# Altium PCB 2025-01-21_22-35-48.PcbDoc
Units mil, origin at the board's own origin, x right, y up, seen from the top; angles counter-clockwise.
Board outline 2000 x 2400 mil, 4 copper layers (Top Layer, MidLayer1, MidLayer2, Bottom Layer); 12 components, 7 nets, 23 pads, 206 vias.
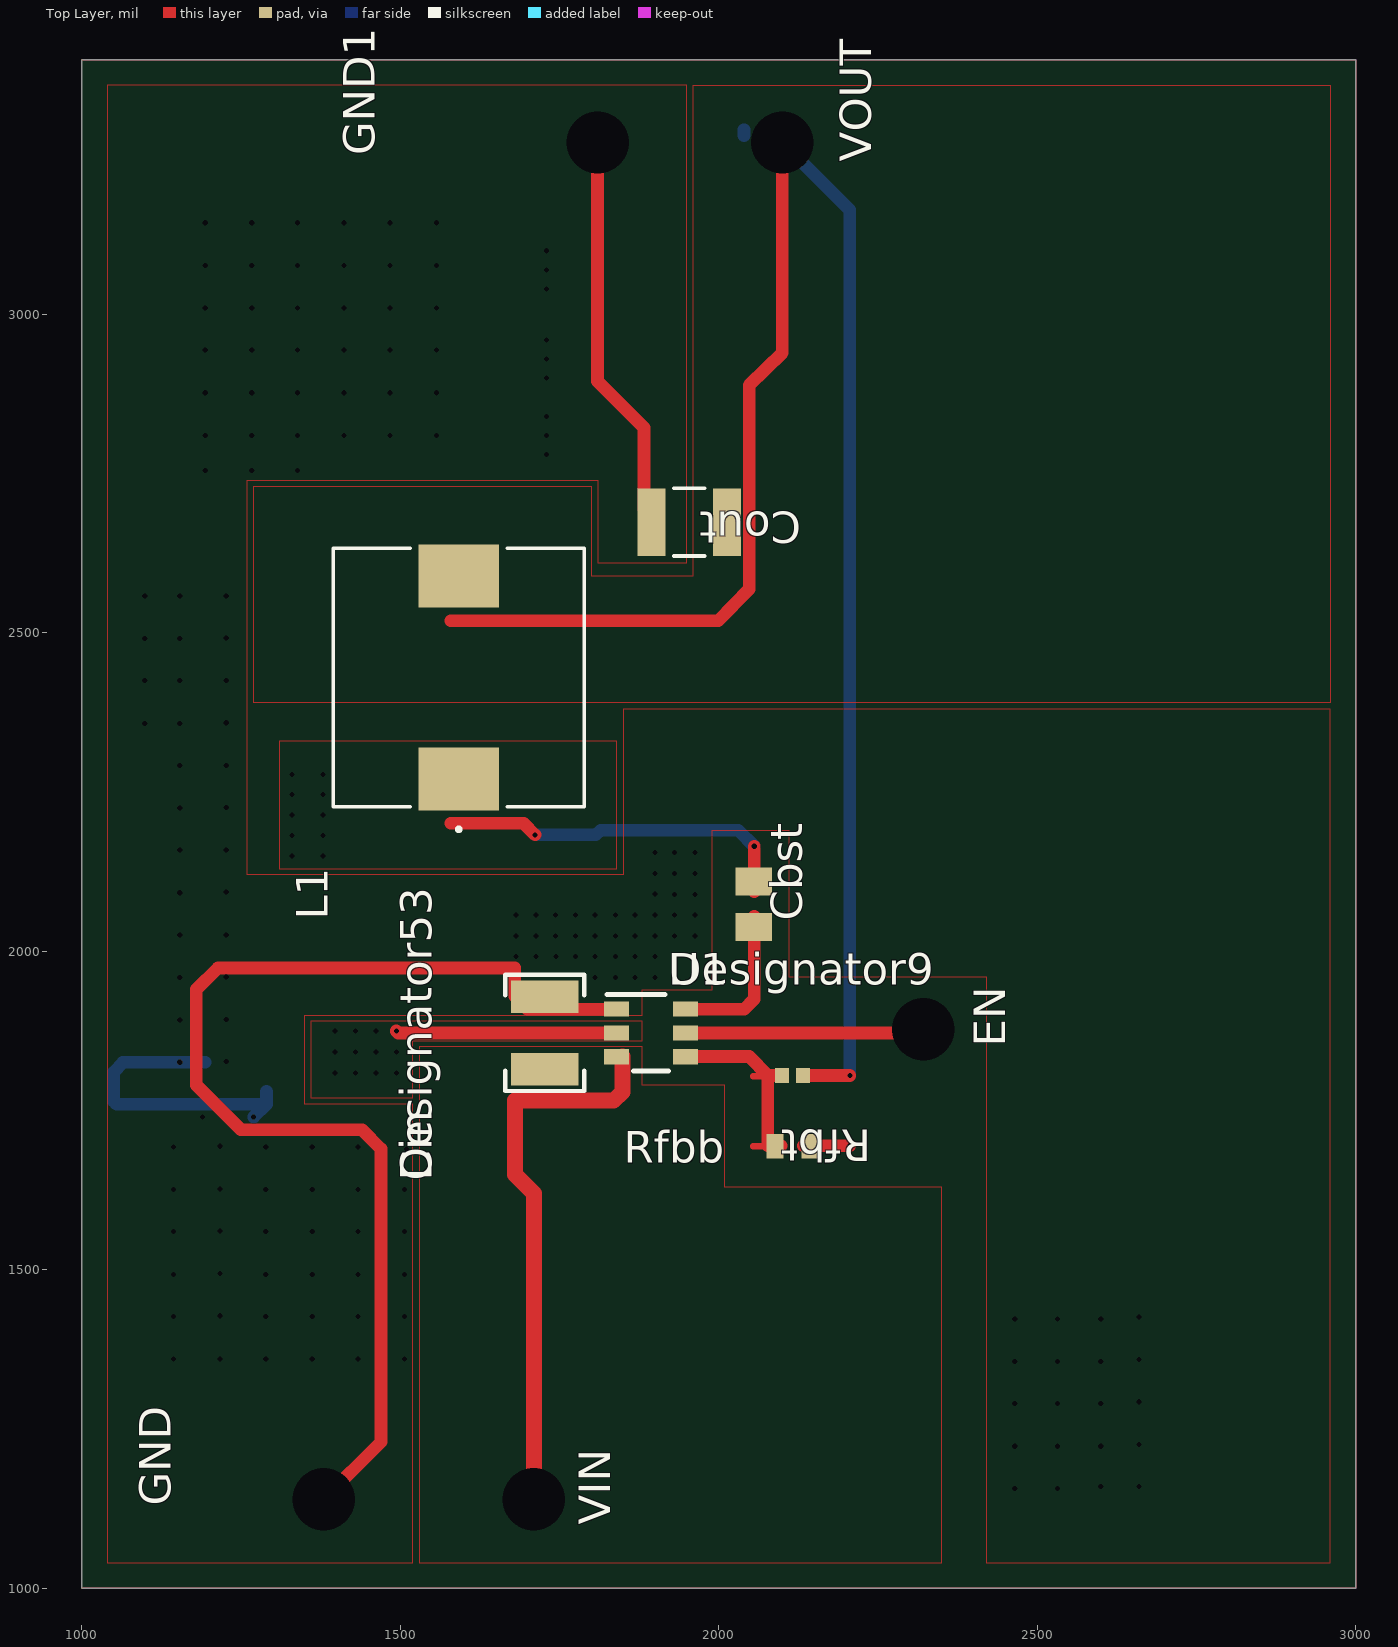
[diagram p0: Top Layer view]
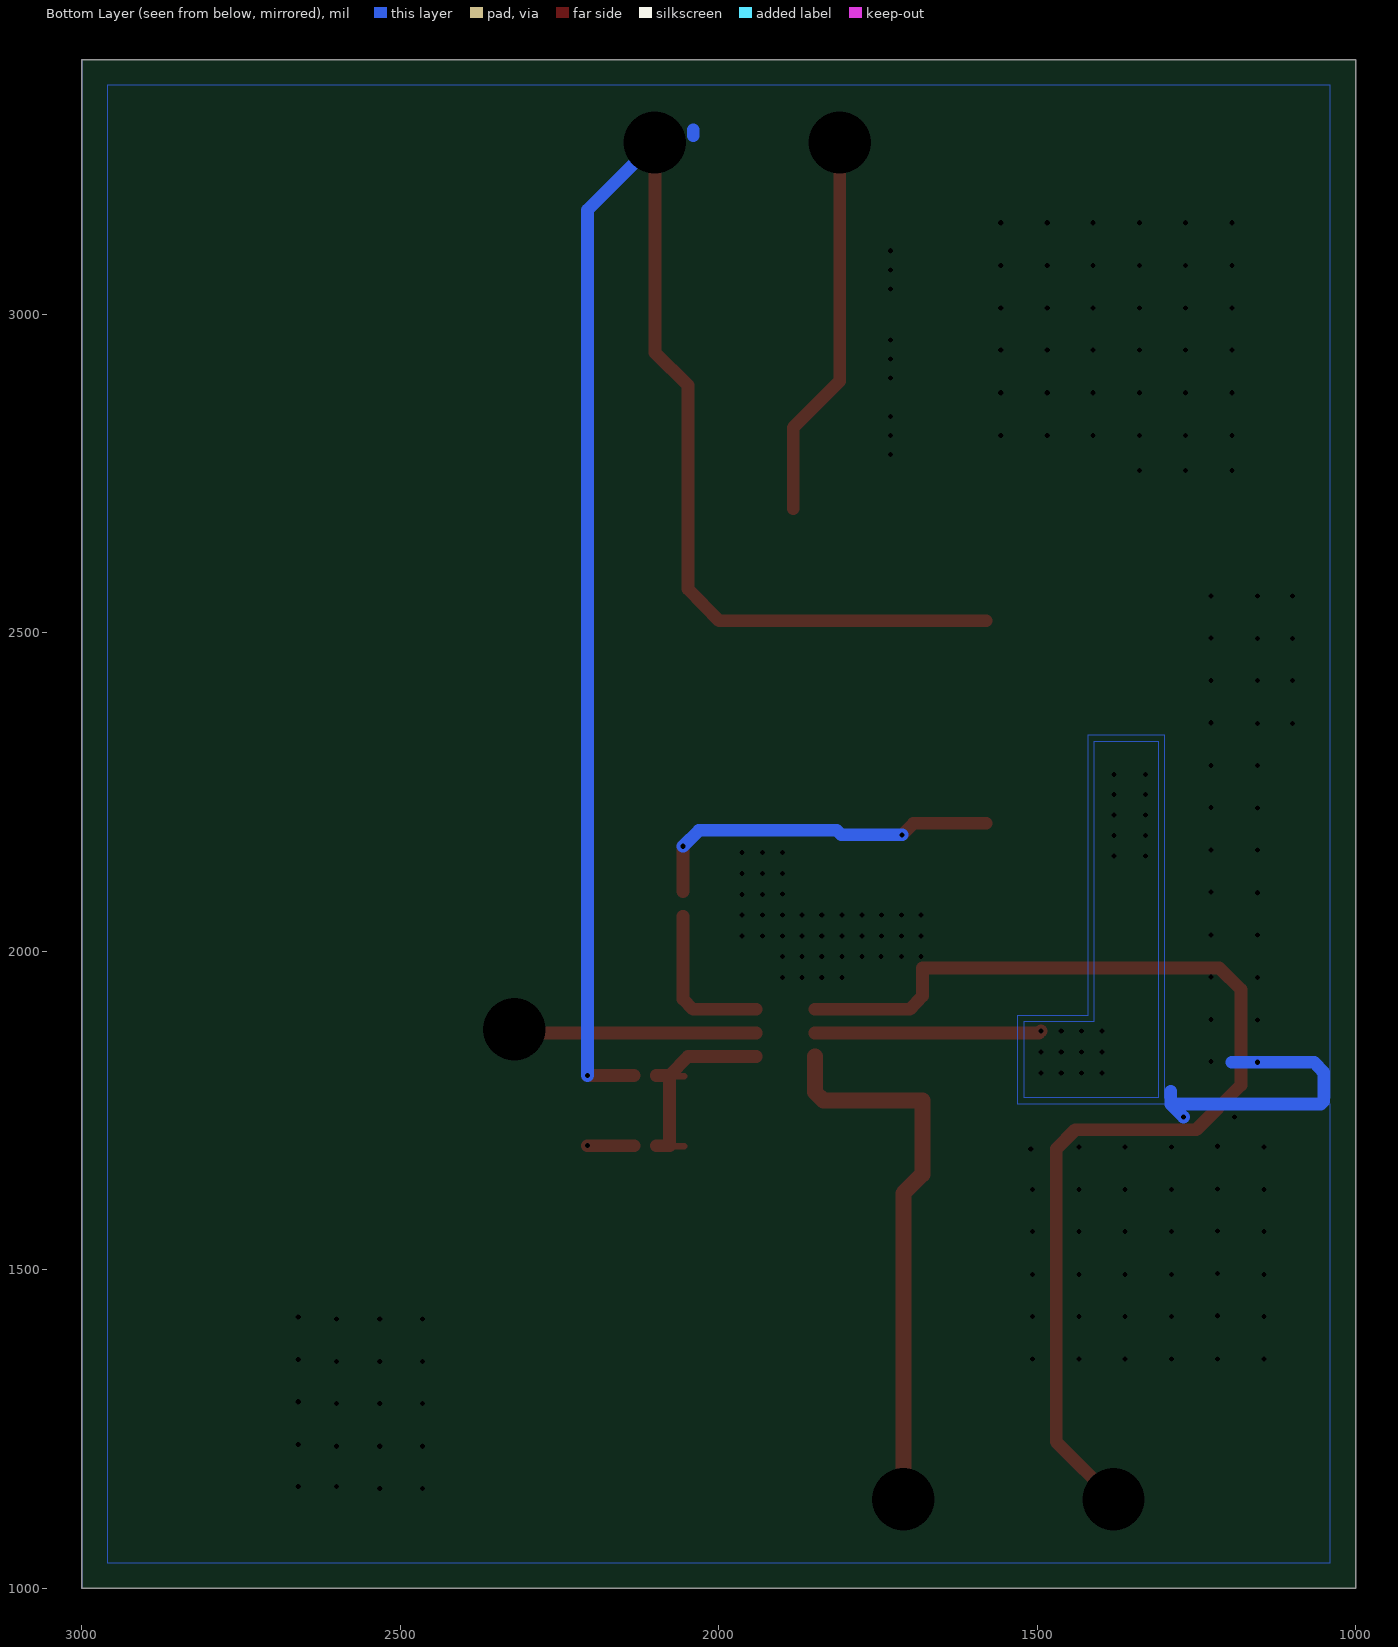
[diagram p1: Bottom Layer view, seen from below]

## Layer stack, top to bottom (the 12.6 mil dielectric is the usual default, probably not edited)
Top Layer: signal copper 1.4
Dielectric: core 12.6, FR-4, Dk 4.8
MidLayer1: signal copper 1.4
Dielectric: prepreg 12.6, FR-4, Dk 4.8
MidLayer2: signal copper 1.4
Dielectric: core 12.6, FR-4, Dk 4.8
Bottom Layer: signal copper 1.4

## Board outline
1000,1000 3000,1000 3000,3400 1000,3400

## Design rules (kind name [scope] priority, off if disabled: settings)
PlaneConnect [All] p0: scope1count=1 scope1_0_kind=Board scope1_0_value=Board scope2count=1 scope2_0_kind=Board scope2_0_value=Board commentlength=0 planeconnectstyle=Direct reliefexpansion=20 reliefentries=4 reliefconductorwidth=10 reliefairgap=10
PlaneConnect [All] p1: planeconnectstyle=Direct reliefexpansion=20 reliefentries=4 reliefconductorwidth=10 reliefairgap=10
PolygonConnect [All] p0: scope1count=1 scope1_0_kind=Board scope1_0_value=Board scope2count=1 scope2_0_kind=Board scope2_0_value=Board commentlength=0 connectstyle=Direct reliefconductorwidth=10 reliefentries=4 polygonreliefangle="90 Angle"
PolygonConnect [All] p1: connectstyle=Direct reliefconductorwidth=10 reliefentries=4 polygonreliefangle="90 Angle"

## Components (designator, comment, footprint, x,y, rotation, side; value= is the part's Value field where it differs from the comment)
Cbst "" 0805 2055,2074 r90 top
Cin "" 1210_270 1727,1872 r90 top
Cout "" 1210_280 1954,2674 r180 top
EN "" TP-1502 2320,1877 r90 top
GND "" TP-1502 1379,1139 r90 top
GND1 "" TP-1502 1809,3269 r90 top
L1 "" CLF10040 1592,2430 r90 top
Rfbb "" 0603 2116,1694 r0 top
Rfbt "" 0402 2116,1805 r180 top
U1 "" DDC0006A_N 1894,1872 r0 top
VIN "" TP-1502 1709,1139 r90 top
VOUT "" TP-1502 2099,3269 r90 top

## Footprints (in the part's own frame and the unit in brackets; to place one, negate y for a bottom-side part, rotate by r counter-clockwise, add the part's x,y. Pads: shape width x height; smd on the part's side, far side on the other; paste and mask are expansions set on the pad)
0402 [mil]
  rect 22x24 smd: 1(-16.5,0) 2(16.5,0)
0603 [mil]
  rect 26x38 smd: 1(-27.5,0) 2(27.5,0)
0805 [mil]
  rect 44x57 smd: 1(-35.5,0) 2(35.5,0)
1210_270 [mm]
  rect 1.3x2.7 smd: 1(-1.45,0) 2(1.45,0)
  silkscreen extent -2.32,-1.57 2.32,1.57
1210_280 [mil]
  rect 44x106 smd: 1(-59,0) 2(59,0)
  silkscreen extent -24,-53 24,53
CLF10040 [mil]
  rect 98.5x126 smd: 1(-159.25,0) 2(159.25,0)
  silkscreen extent -241,-197 203,197
DDC0006A_N [mm]
  rect 1x0.6 smd: 1(-1.375,0.95) 2(-1.375,0) 3(-1.375,-0.95) 4(1.375,-0.95) 5(1.375,0) 6(1.375,0.95)
  silkscreen extent -1.75,-1.52 0.7,1.53
TP-1502 [mil]
  round 65 hole 32: 1(0,0)

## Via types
v1: diameter 0, hole 8, Top Layer to Bottom Layer, 201 vias
v2: diameter 0, hole 98, Top Layer to Bottom Layer, 5 vias

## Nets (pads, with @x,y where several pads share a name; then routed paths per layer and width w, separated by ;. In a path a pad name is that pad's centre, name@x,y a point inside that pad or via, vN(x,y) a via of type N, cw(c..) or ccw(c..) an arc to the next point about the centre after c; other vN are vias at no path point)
0: Cin.2 Cout.2 GND1.1 GND.1 Rfbb.2 U1.1 | length 3046.3
  Top Layer w10: 2130,1694 2177,1694
  Top Layer w20: v2(1380,1140) 1470,1230 1470,1690 1440,1720 1250,1720 1180,1790 1180,1940 1214,1974 1680,1974 1680,1930 1700,1909 U1.1@1849,1909 ; 1400,1110 GND.1@1400,1140 ; v2(1810,3270) 1810,2895 1883,2822 Cout.2@1883,2695 ; Rfbb.2@2133,1695 2154,1695 v1(2206,1695)
  Bottom Layer w20: 1194,1826 v1(1154,1826) 1065,1826 1050,1810 1050,1765 1055,1760 1290,1760 ; v1(1270,1740) 1290,1760 ; 1290,1780 1290,1760
  other v1: 2465,1157 2532,1157 2600,1160 2660,1160 2465,1223 2532,1223 2600,1223 2660,1226 2465,1290 2532,1290 2600,1290 2660,1293 2465,1356 2532,1356 2600,1356 2660,1359 1144,1360 1217,1360 1289,1360 1362,1360 1434,1360 1507,1360 2465,1423 2532,1423 2600,1423 2660,1426 1144,1427 1289,1427 1362,1427 1434,1427 1507,1427 1217,1428 1144,1493 1289,1493 1362,1493 1434,1493 1507,1493 1217,1494 1144,1560 1289,1560 1362,1560 1434,1560 1507,1560 1217,1561 1144,1626 1289,1626 1362,1626 1434,1626 1507,1626 1217,1627 1510,1690 1144,1693 1289,1693 1362,1693 1434,1693 1217,1694 1190,1740 1227,1827 1154,1892 1227,1893 1154,1959 1806,1959 1838,1959 1869,1959 1900,1959 1227,1960 1682,1992 1713,1992 1745,1992 1775,1992 1806,1992 1838,1992 1869,1992 1900,1992 1682,2024 1713,2024 1744,2024 1775,2024 1806,2024 1838,2024 1869,2024 1900,2024 1931,2024 1963,2024 1154,2026 1227,2026 1682,2057 1713,2057 1744,2057 1775,2057 1806,2057 1838,2057 1869,2057 1900,2057 1931,2057 1963,2057 1931,2089 1963,2089 1900,2090 1154,2092 1227,2093 1900,2122 1931,2122 1963,2122 1900,2155 1931,2155 1963,2155 1154,2159 1227,2159 1154,2225 1227,2226 1154,2292 1227,2292 1099,2358 1154,2358 1227,2359 1099,2425 1154,2425 1227,2425 1099,2491 1154,2491 1227,2492 1099,2558 1154,2558 1227,2558 1194,2755 1267,2755 1339,2755 1730,2780 1194,2810 1267,2810 1339,2810 1412,2810 1484,2810 1557,2810 1730,2810 1730,2840 1194,2877 1267,2877 1339,2877 1412,2877 1484,2877 1557,2877 1730,2900 1730,2930 1194,2944 1267,2944 1339,2944 1412,2944 1484,2944 1557,2944 1730,2960 1194,3010 1267,3010 1339,3010 1412,3010 1484,3010 1557,3010 1730,3040 1730,3070 1194,3077 1267,3077 1339,3077 1412,3077 1484,3077 1557,3077 1730,3100 1194,3144 1267,3144 1339,3144 1412,3144 1484,3144 1557,3144
1: Rfbb.1 Rfbt.2 U1.4 | length 394.7
  Top Layer w10: 2054,1694 Rfbb.1@2101,1694 ; 2054,1804 Rfbt.2@2101,1804
  Top Layer w20: U1.4@1941,1835 2048,1835 2077,1805 ; Rfbb.1@2098,1695 2077,1695 2077,1805 ; Rfbt.2@2098,1805 2077,1805
2: Cbst.2 L1.1 U1.2 | length 970.7
  Top Layer w10: Cbst.2@2055,2090 2055,2137
  Top Layer w20: v1(1494,1875) 1497,1872 U1.2@1849,1872 ; 1580,2201 1694,2201 v1(1712,2183) ; Cbst.2@2056,2094 2056,2113 v1(2056,2165)
  Bottom Layer w20: v1(1712,2183) 1807,2183 1815,2190 2031,2190 v1(2056,2165)
  other v1: 1398,1809 1430,1809 1462,1809 1494,1809 1398,1842 1430,1842 1462,1842 1494,1842 1398,1875 1430,1875 1462,1875 1330,2150 1379,2150 1330,2182 1379,2182 1330,2214 1379,2214 1330,2246 1379,2246 1330,2278 1379,2278
4: Cout.1 L1.2 Rfbt.1 VOUT.1 | length 2869.7
  Top Layer w10: Rfbt.1@2130,1804 2177,1804
  Top Layer w20: 1580,2519 1999,2519 2048,2569 2048,2695 2048,2889 2100,2940 v2(2100,3270) VOUT.1@2100,3290 ; Rfbt.1@2133,1805 2154,1805 v1(2206,1805)
  Bottom Layer w20: 2040,3281 2040,3290 ; v2(2100,3270) 2206,3164 v1(2206,1805)
6: Cin.1 U1.3 VIN.1 | length 868.5
  Top Layer w25: v2(1710,1140) 1710,1620 1680,1650 1680,1766 1835,1766 1849,1779 U1.3@1849,1835
10: EN.1 U1.5 | length 382.5
  Top Layer w20: U1.5@1941,1872 2315,1872 v2(2321,1878)
11: Cbst.1 U1.6 | length 298.6
  Top Layer w10: 2055,2013 Cbst.1@2055,2060
  Top Layer w20: U1.6@1941,1909 2040,1909 2056,1925 Cbst.1@2056,2055

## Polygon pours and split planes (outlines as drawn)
6 on Top Layer " " (solid, pour order 0): 1880,1850 1530,1850 1530,1040 2350,1040 2350,1630 2010,1630 2010,1790 1880,1790
2 on Top Layer " " (solid, pour order 1): 1880,1860 1880,1890 1360,1890 1360,1770 1520,1770 1520,1860
2 on Top Layer " " (solid, pour order 2): 1310,2130 1840,2130 1840,2330 1310,2330
4 on Top Layer " " (solid, pour order 3): 1270,2730 1800,2730 1800,2590 1960,2590 1960,3360 2960,3360 2960,2390 1270,2390
0 on Top Layer " " (solid, pour order 5): 1260,2740 1810,2740 1810,2610 1950,2610 1950,3360 1040,3360 1040,1040 1520,1040 1520,1760 1350,1760 1350,1900 1880,1900 1880,1940 1990,1940 1990,2190 2110,2190 2110,1960 2420,1960 2420,1040 2960,1040 2960,2380 1850,2380 1850,2120 1260,2120
2 on Bottom Layer " " (solid, pour order 4): 1520,1890 1410,1890 1410,2330 1310,2330 1310,1770 1520,1770
0 on Bottom Layer " " (solid, pour order 6): 1040,3360 2960,3360 2960,1040 1040,1040 1040,1760 1530,1760 1530,1900 1420,1900 1420,2340 1300,2340 1300,1770 1040,1770

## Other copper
Multi-Layer:
  the board outline again, w1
